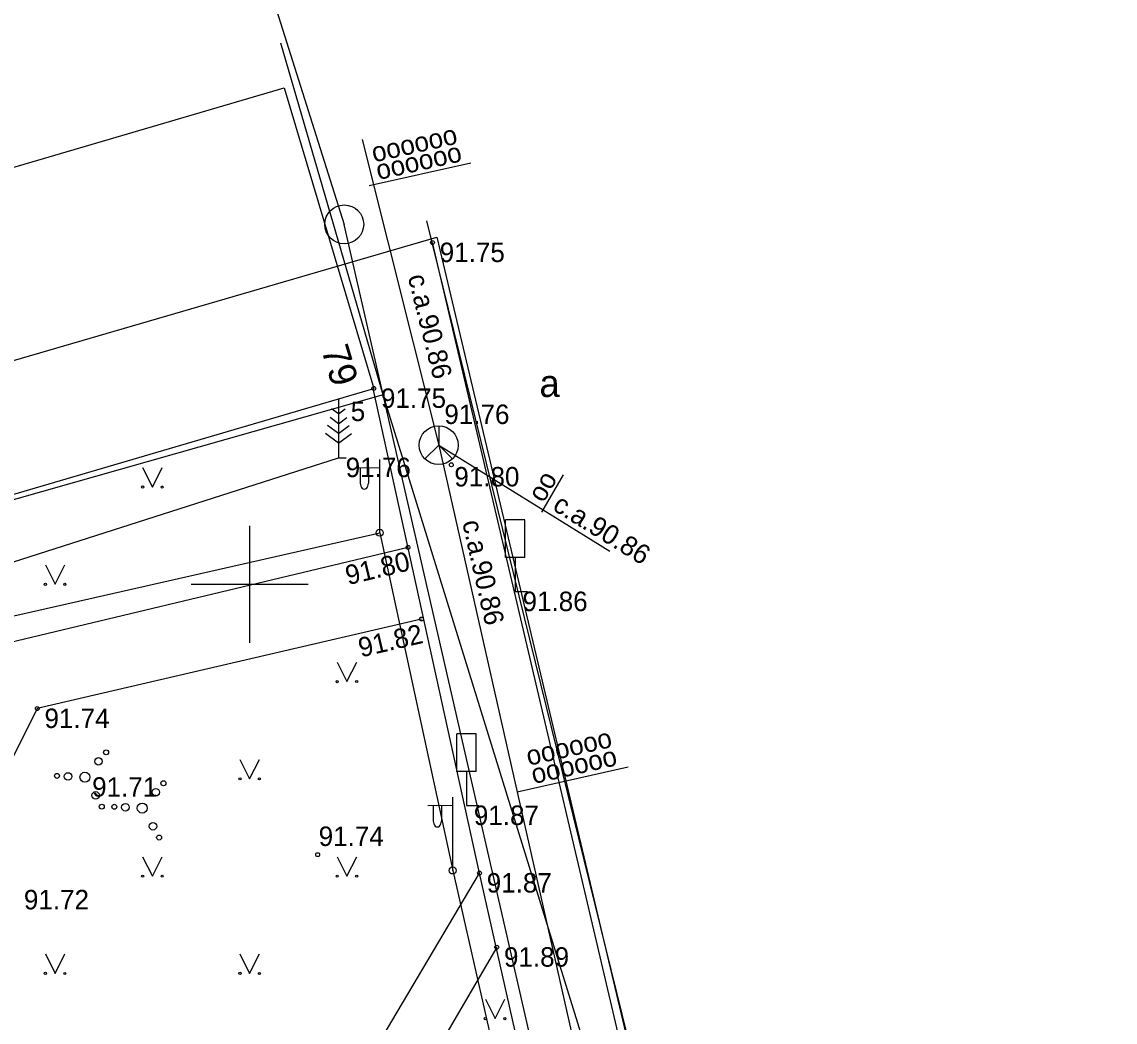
# Model space of a CAD drawing. Extents: x 634272 to 634544, y 247463 to 247653.
# Drawn here: x 634444.15 to 634472.24, y 247588.75 to 247614.46 of the extents above; entities that cross this region are included whole.
import ezdxf

# ---------------------------------------------------------------- set-up
doc = ezdxf.new("R2010")
doc.units = 0
for name, color, linetype in [('APGR_ELEM_####_####_#', 7, 'Continuous'), ('APGR_SARK_####_####_#', 7, 'Continuous'), ('APGS_ELEM_####_####_#', 7, 'Continuous'), ('APGS_VADP_ZSPR_####_#', 7, 'Continuous'), ('BUVE_EKAS_####_####_#', 7, 'Continuous'), ('BUVE_EKAS_ADRS_TKST_#', 7, 'Continuous'), ('CELI_CAPM_####_####_#', 7, 'Continuous'), ('CELI_CMAL_####_####_#', 7, 'Continuous'), ('CELI_CSEG_####_TKST_#', 7, 'Continuous'), ('CELI_ELEM_####_####_#', 7, 'Continuous'), ('GEOD_ELEM_####_####_#', 7, 'Continuous'), ('NORB_ZOGS_ZMET_####_#', 7, 'Continuous'), ('RAMI_UZMR_####_####_#', 7, 'Continuous'), ('RELJ_AATZ_####_TKST_#', 7, 'Continuous'), ('RELJ_ELEM_####_####_#', 7, 'Continuous'), ('ROBZ_PROJ_####_####_#', 7, 'Continuous'), ('ROBZ_UZMR_####_####_#', 7, 'Continuous'), ('SAKK_ELEM_####_####_#', 7, 'Continuous'), ('SAKK_ELEM_####_TKST_#', 7, 'Continuous'), ('SAKK_IZVK_####_TKST_#', 7, 'Continuous'), ('SAKK_KKAN_####_####_#', 7, 'Continuous'), ('SAKK_KKAN_####_TKST_#', 7, 'Continuous'), ('TERT_DIAM_####_TKST_#', 7, 'Continuous'), ('TERT_ELEM_####_####_#', 7, 'Continuous'), ('TERT_KOKR_####_####_#', 7, 'Continuous')]:
    doc.layers.add(name, color=color, linetype=linetype)

msp = doc.modelspace()

# ---------------------------------------------------------------- linework, layer by layer
at = {"layer": 'APGR_ELEM_####_####_#'}
msp.add_circle((634452.43, 247609.25), 0.5, dxfattribs=at)
at = {"layer": 'APGR_SARK_####_####_#'}
for p in [(634448.985, 247620.146), (634472.239, 247522.641)]:
    msp.add_line(p, (634452.431, 247609.249), dxfattribs=at)
at = {"layer": 'APGS_ELEM_####_####_#'}
for p, q in [((634453.341, 247601.325), (634453.341, 247603.208)), ((634453.341, 247602.992), (634452.706, 247602.987)), ((634452.841, 247602.988), (634452.841, 247602.596)), ((634453.051, 247602.99), (634453.051, 247602.596)), ((634455.217, 247592.645), (634455.217, 247594.528)), ((634455.217, 247594.312), (634454.582, 247594.307)), ((634454.717, 247594.308), (634454.717, 247593.916)), ((634454.927, 247594.31), (634454.927, 247593.916))]:
    msp.add_line(p, q, dxfattribs=at)
for centre in [(634453.341, 247601.325), (634455.217, 247592.645)]:
    msp.add_circle(centre, 0.09, dxfattribs=at)
for centre in [(634452.946, 247602.596), (634454.822, 247593.916)]:
    msp.add_ellipse(centre, major_axis=(0, 0.151), ratio=0.695971, start_param=1.570796, end_param=4.712389, dxfattribs=at)
at = {"layer": 'APGS_VADP_ZSPR_####_#'}
msp.add_lwpolyline([(634424.64, 247564.493), (634427.489, 247567.387), (634428.243, 247568.282), (634428.556, 247569.174), (634428.62, 247569.734), (634428.349, 247570.951), (634427.518, 247573.97), (634425.055, 247583.293), (634424.177, 247586.368), (634423.255, 247589.552), (634422.487, 247592.599), (634438.755, 247598.02), (634453.341, 247601.325), (634455.217, 247592.645), (634458.049, 247580.186), (634460.842, 247567.679), (634446.181, 247564.209)], dxfattribs=at)
at = {"layer": 'BUVE_EKAS_####_####_#'}
for points in [[(634430.752, 247606.848), (634450.886, 247612.763)], [(634450.886, 247612.763), (634453.188, 247605.034)], [(634433.054, 247599.119), (634453.188, 247605.034)]]:
    msp.add_lwpolyline(points, dxfattribs=at)
at = {"layer": 'CELI_CAPM_####_####_#'}
msp.add_lwpolyline([(634462.278, 247564.311), (634455.906, 247592.579), (634453.174, 247605.031)], dxfattribs=at)
at = {"layer": 'CELI_CMAL_####_####_#'}
for points in [[(634472.031, 247532.571), (634469.381, 247545.11), (634466.419, 247558.939), (634461.107, 247582.724), (634454.551, 247609.343)], [(634454.07, 247600.948), (634439.005, 247597.351), (634440.194, 247592.28), (634435.446, 247582.728), (634431.634, 247584.56), (634429.222, 247594.101)], [(634454.416, 247599.108), (634444.542, 247596.807), (634437.329, 247582.391), (634445.746, 247584.585), (634452.082, 247586.129), (634455.906, 247592.579)], [(634456.349, 247590.673), (634453.418, 247585.656), (634458.133, 247582.79)]]:
    msp.add_lwpolyline(points, dxfattribs=at)
at = {"layer": 'CELI_ELEM_####_####_#'}
for p, q in [((634457.072, 247601.659), (634456.572, 247601.659)), ((634456.572, 247600.69), (634456.572, 247601.659)), ((634457.072, 247600.69), (634457.072, 247601.659)), ((634457.072, 247600.69), (634456.572, 247600.69)), ((634456.826, 247600.69), (634456.826, 247599.812)), ((634456.826, 247599.812), (634457.141, 247599.812)), ((634455.821, 247596.161), (634455.321, 247596.161)), ((634455.321, 247595.192), (634455.321, 247596.161)), ((634455.821, 247595.192), (634455.821, 247596.161)), ((634455.821, 247595.192), (634455.321, 247595.192)), ((634455.575, 247595.192), (634455.575, 247594.314)), ((634455.575, 247594.314), (634455.89, 247594.314))]:
    msp.add_line(p, q, dxfattribs=at)
at = {"layer": 'GEOD_ELEM_####_####_#'}
for p, q in [((634450, 247601.5), (634450, 247600)), ((634448.5, 247600), (634450, 247600)), ((634450, 247600), (634450, 247598.5)), ((634450, 247600), (634451.5, 247600))]:
    msp.add_line(p, q, dxfattribs=at)
at = {"layer": 'NORB_ZOGS_ZMET_####_#'}
msp.add_lwpolyline([(634464.866, 247565.466), (634454.698, 247608.782)], dxfattribs=at)
at = {"layer": 'RAMI_UZMR_####_####_#'}
msp.add_lwpolyline([(634357.63, 247590.775), (634379.264, 247596.642), (634392.424, 247602.216), (634402.994, 247605.715), (634421.735, 247609.504), (634423.082, 247609.702), (634425.783, 247608.304), (634427.755, 247600.855), (634433.048, 247602.581), (634454.806, 247608.92), (634459.819, 247587.798), (634462.766, 247575.147), (634466.614, 247558.36), (634469.076, 247546.545)], dxfattribs=at)
at = {"layer": 'RELJ_ELEM_####_####_#'}
for centre in [(634454.698, 247608.782), (634453.188, 247605.034), (634455.183, 247603.072), (634454.07, 247600.948), (634454.416, 247599.108), (634444.542, 247596.807), (634451.748, 247593.052), (634455.906, 247592.579), (634456.349, 247590.673)]:
    msp.add_circle(centre, 0.05, dxfattribs=at)
at = {"layer": 'ROBZ_PROJ_####_####_#'}
msp.add_lwpolyline([(634465.768, 247565.048), (634453.433, 247604.869)], dxfattribs=at)
at = {"layer": 'ROBZ_UZMR_####_####_#'}
for points in [[(634453.433, 247604.869), (634450.805, 247613.909)], [(634453.433, 247604.869), (634439.274, 247600.849)]]:
    msp.add_lwpolyline(points, dxfattribs=at)
at = {"layer": 'SAKK_ELEM_####_####_#'}
msp.add_line((634454.857, 247603.576), (634455.211, 247603.222), dxfattribs=at)
msp.add_lwpolyline([(634454.857, 247604.076), (634454.857, 247603.576), (634454.503, 247603.222)], dxfattribs=at)
msp.add_circle((634454.857, 247603.576), 0.5, dxfattribs=at)
at = {"layer": 'SAKK_IZVK_####_TKST_#'}
for p, q in [((634453.075, 247610.249), (634455.681, 247610.836)), ((634457.507, 247601.85), (634458.061, 247602.81)), ((634456.87, 247594.667), (634459.722, 247595.31))]:
    msp.add_line(p, q, dxfattribs=at)
at = {"layer": 'SAKK_KKAN_####_####_#'}
for points in [[(634452.888, 247611.435), (634454.857, 247603.576), (634466.565, 247551.758), (634472.201, 247519.993)], [(634454.857, 247603.576), (634459.252, 247600.855)]]:
    msp.add_lwpolyline(points, dxfattribs=at)
at = {"layer": 'TERT_ELEM_####_####_#'}
for p, q in [((634452.282, 247604.754), (634452.282, 247603.254)), ((634452.282, 247604.378), (634452.106, 247604.506)), ((634452.282, 247604.378), (634452.456, 247604.506)), ((634452.282, 247603.878), (634452.004, 247604.082)), ((634452.282, 247604.128), (634452.066, 247604.286)), ((634452.282, 247604.128), (634452.498, 247604.286)), ((634452.282, 247603.878), (634452.56, 247604.082)), ((634452.282, 247603.628), (634451.95, 247603.872)), ((634452.282, 247603.628), (634452.616, 247603.872)), ((634452.282, 247603.254), (634452.482, 247603.254)), ((634447.25, 247603), (634447.5, 247602.5)), ((634447.5, 247602.5), (634447.75, 247603)), ((634444.75, 247600.5), (634445, 247600)), ((634445, 247600), (634445.25, 247600.5)), ((634452.25, 247598), (634452.5, 247597.5)), ((634452.5, 247597.5), (634452.75, 247598)), ((634449.75, 247595.5), (634450, 247595)), ((634450, 247595), (634450.25, 247595.5)), ((634447.25, 247593), (634447.5, 247592.5)), ((634447.5, 247592.5), (634447.75, 247593)), ((634452.25, 247593), (634452.5, 247592.5)), ((634452.5, 247592.5), (634452.75, 247593)), ((634444.75, 247590.5), (634445, 247590)), ((634445, 247590), (634445.25, 247590.5)), ((634449.75, 247590.5), (634450, 247590)), ((634450, 247590), (634450.25, 247590.5)), ((634456.056, 247589.338), (634456.306, 247588.838)), ((634456.306, 247588.838), (634456.556, 247589.338))]:
    msp.add_line(p, q, dxfattribs=at)
for centre, radius in [((634447.25, 247602.5), 0.028), ((634447.75, 247602.5), 0.0263), ((634444.75, 247600), 0.028), ((634445.25, 247600), 0.0263), ((634452.25, 247597.5), 0.028), ((634452.75, 247597.5), 0.0263), ((634446.311, 247595.681), 0.064), ((634446.115, 247595.45), 0.096), ((634445.049, 247595.076), 0.064), ((634445.333, 247595.063), 0.096), ((634445.767, 247595.042), 0.128), ((634447.784, 247594.887), 0.064), ((634449.75, 247595), 0.028), ((634450.25, 247595), 0.0263), ((634446.043, 247594.575), 0.096), ((634447.588, 247594.656), 0.096), ((634446.201, 247594.286), 0.064), ((634446.522, 247594.282), 0.064), ((634446.806, 247594.269), 0.096), ((634447.24, 247594.248), 0.128), ((634447.516, 247593.781), 0.096), ((634447.674, 247593.492), 0.064), ((634447.25, 247592.5), 0.028), ((634452.25, 247592.5), 0.028), ((634447.75, 247592.5), 0.0263), ((634452.75, 247592.5), 0.0263), ((634444.75, 247590), 0.028), ((634445.25, 247590), 0.0263), ((634449.75, 247590), 0.028), ((634450.25, 247590), 0.0263), ((634456.055, 247588.837), 0.028), ((634456.555, 247588.837), 0.0263)]:
    msp.add_circle(centre, radius, dxfattribs=at)
at = {"layer": 'TERT_KOKR_####_####_#'}
msp.add_lwpolyline([(634440.261, 247599.404), (634452.282, 247603.254)], dxfattribs=at)

# ---------------------------------------------------------------- texts
at = {"layer": 'BUVE_EKAS_ADRS_TKST_#'}
msp.add_text('79', height=0.7, rotation=286.5856, dxfattribs=at).set_placement((634451.836, 247606.035))
at = {"layer": 'CELI_CSEG_####_TKST_#'}
msp.add_text('a', height=0.7, dxfattribs=at).set_placement((634457.446, 247604.815))
at = {"layer": 'RELJ_AATZ_####_TKST_#'}
for s, p in [(' 91.75', (634454.698, 247608.282)), (' 91.75', (634453.188, 247604.534)), (' 91.76', (634452.282, 247602.754)), (' 91.80', (634455.073, 247602.515)), (' 91.86', (634456.826, 247599.312)), (' 91.74', (634444.542, 247596.307)), (' 91.71', (634445.767, 247594.542)), (' 91.87', (634455.575, 247593.814)), (' 91.74', (634451.588, 247593.275)), (' 91.87', (634455.906, 247592.079)), (' 91.72', (634444.013, 247591.646)), (' 91.89', (634456.349, 247590.173))]:
    msp.add_text(s, height=0.5, dxfattribs=at).set_placement(p)
for s, rotation, p in [(' 91.80', 13.4288, (634452.347, 247599.935)), (' 91.82', 13.1179, (634452.678, 247598.077))]:
    msp.add_text(s, height=0.5, rotation=rotation, dxfattribs=at).set_placement(p)
at = {"layer": 'SAKK_ELEM_####_TKST_#'}
msp.add_text(' 91.76', height=0.5, dxfattribs=at).set_placement((634454.817, 247604.12))
at = {"layer": 'SAKK_IZVK_####_TKST_#'}
for s, rotation, p in [('oooooo', 12.6975, (634453.195, 247610.841)), ('oooooo', 12.6975, (634453.308, 247610.389)), ('oo', 59.9817, (634457.549, 247602.074)), ('oooooo', 12.6975, (634457.169, 247595.334)), ('oooooo', 12.6975, (634457.298, 247594.866))]:
    msp.add_text(s, height=0.5, rotation=rotation, dxfattribs=at).set_placement(p)
at = {"layer": 'SAKK_KKAN_####_TKST_#'}
for rotation, p in [(284.0646, (634454.059, 247607.907)), (328.2444, (634457.753, 247601.929)), (282.7319, (634455.458, 247601.596))]:
    msp.add_text('c.a.90.86', height=0.5, rotation=rotation, dxfattribs=at).set_placement(p)
at = {"layer": 'TERT_DIAM_####_TKST_#'}
msp.add_text('5', height=0.5, dxfattribs=at).set_placement((634452.597, 247604.196))

doc.saveas('drawing.dxf')
